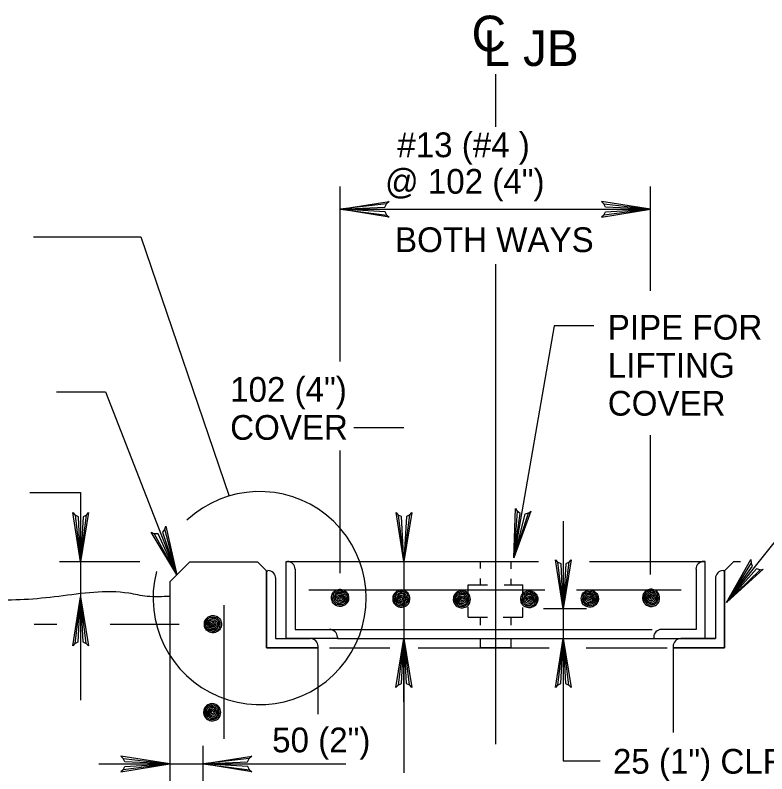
# Model space of a CAD drawing. Extents: x 638455 to 640199, y 298558 to 299152.
# Drawn here: x 639434 to 639536, y 298749 to 298852 of the extents above; entities that cross this region are included whole.
import ezdxf

# ---------------------------------------------------------------- set-up
doc = ezdxf.new("R2010")
doc.units = 0
for name, color, linetype in [('1', 7, 'Continuous'), ('2', 7, 'Continuous'), ('3', 7, 'Continuous')]:
    doc.layers.add(name, color=color, linetype=linetype)

msp = doc.modelspace()

# ---------------------------------------------------------------- linework, layer by layer
at = {"layer": '1'}
msp.add_line((639530.53, 298772.26), (639540.8, 298785.17), dxfattribs=at)
msp.add_arc((639467.17, 298772.88), 14.46, 165.5943, 133.0087, dxfattribs=at)
at = {"layer": '2'}
for p, q in [((639499.18, 298844), (639499.18, 298836.83)), ((639478.09, 298804.97), (639478.09, 298828.74)), ((639520.19, 298814.59), (639520.19, 298828.74)), ((639478.09, 298825.65), (639520.19, 298825.65)), ((639436.5, 298821.91), (639451.03, 298821.91)), ((639451.03, 298821.91), (639463.02, 298786.73)), ((639499.18, 298818.19), (639499.18, 298753.05)), ((639507.12, 298809.85), (639501.68, 298778.32)), ((639512.51, 298809.85), (639507.12, 298809.85)), ((639439.61, 298800.88), (639446.26, 298800.88)), ((639446.26, 298800.88), (639455.94, 298776.05)), ((639479.95, 298796.04), (639486.74, 298796.04)), ((639520.19, 298776.09), (639520.19, 298795)), ((639478.09, 298776.26), (639478.09, 298792.9)), ((639435.97, 298787.22), (639442.88, 298787.22)), ((639442.88, 298787.22), (639442.88, 298777.82)), ((639508.37, 298783.31), (639508.37, 298771.43)), ((639450.92, 298777.82), (639440, 298777.82)), ((639454.98, 298775.09), (639457.72, 298777.82)), ((639457.72, 298777.82), (639466.88, 298777.82)), ((639466.88, 298777.82), (639468.11, 298776.59)), ((639470.75, 298777.84), (639470.93, 298777.84)), ((639470.75, 298777.84), (639505.02, 298777.84)), ((639486.74, 298777.84), (639486.74, 298749.14)), ((639497.1, 298777.84), (639497.1, 298776.91)), ((639501.27, 298777.84), (639501.27, 298776.86)), ((639511.95, 298777.84), (639527.62, 298777.84)), ((639527.62, 298777.84), (639527.43, 298777.84)), ((639527.43, 298777.84), (639527.43, 298777.84)), ((639468.11, 298776.59), (639468.3, 298776.59)), ((639468.11, 298776.59), (639468.11, 298766.14)), ((639530.26, 298776.59), (639530.07, 298776.59)), ((639530.26, 298776.59), (639530.26, 298766.14)), ((639454.98, 298775.09), (639454.98, 298714.23)), ((639495.47, 298773.34), (639495.47, 298774.69)), ((639495.47, 298774.69), (639498.09, 298774.69)), ((639497.1, 298775.53), (639497.1, 298774.69)), ((639500.37, 298774.69), (639502.9, 298774.69)), ((639501.27, 298775.49), (639501.27, 298774.69)), ((639502.9, 298773.46), (639502.9, 298774.69)), ((639473.85, 298774.01), (639505.86, 298774.01)), ((639510.16, 298774.01), (639524.37, 298774.01)), ((639462.3, 298771.9), (639462.3, 298753.77)), ((639495.47, 298770.28), (639495.47, 298771.66)), ((639502.9, 298770.28), (639502.9, 298771.61)), ((639511.54, 298771.43), (639505.69, 298771.43)), ((639508.37, 298771.43), (639508.37, 298767.39)), ((639495.47, 298770.28), (639498.09, 298770.28)), ((639497.1, 298770.28), (639497.1, 298769.21)), ((639500.2, 298770.28), (639502.9, 298770.28)), ((639501.27, 298770.28), (639501.27, 298769.21)), ((639439.66, 298769.27), (639436.56, 298769.27)), ((639456.25, 298769.27), (639446.88, 298769.27)), ((639476.67, 298768.62), (639520.43, 298768.62)), ((639477.72, 298767.57), (639477.72, 298767.39)), ((639477.72, 298767.39), (639529.02, 298767.39)), ((639480.16, 298767.39), (639492.28, 298767.39)), ((639486.74, 298758.79), (639486.74, 298767.39)), ((639497.1, 298767.39), (639497.1, 298766.17)), ((639497.44, 298767.39), (639500.93, 298767.39)), ((639498.6, 298767.39), (639507.79, 298767.39)), ((639501.27, 298767.39), (639501.27, 298766.17)), ((639508.37, 298767.39), (639508.37, 298750.77)), ((639520.65, 298767.57), (639520.65, 298767.39)), ((639475.08, 298766.32), (639475.08, 298766.14)), ((639523.29, 298766.32), (639523.29, 298766.14)), ((639468.11, 298766.14), (639475.08, 298766.14)), ((639475.08, 298766.14), (639475.08, 298757.12)), ((639476.67, 298766.14), (639484.84, 298766.14)), ((639488.66, 298766.14), (639506.46, 298766.14)), ((639497.1, 298766.17), (639501.27, 298766.17)), ((639511.47, 298766.14), (639522.46, 298766.14)), ((639530.26, 298766.14), (639523.29, 298766.14)), ((639523.29, 298766.14), (639523.29, 298754.61)), ((639459.45, 298752.82), (639459.45, 298745.89)), ((639445.33, 298750.37), (639459.45, 298750.37)), ((639459.45, 298750.37), (639478.87, 298750.37)), ((639508.37, 298750.77), (639513.38, 298750.77))]:
    msp.add_line(p, q, dxfattribs=at)
for points in [[(639484.42, 298824.86), (639484.19, 298825.32), (639478.09, 298825.65), (639484.42, 298824.86), (639484.75, 298824.58), (639478.09, 298825.65), (639484.18, 298825.95), (639484.4, 298826.4), (639478.09, 298825.65), (639484.75, 298826.71), (639484.4, 298826.4)], [(639513.86, 298824.86), (639514.1, 298825.32), (639520.19, 298825.65), (639513.86, 298824.86), (639513.54, 298824.58), (639520.19, 298825.65), (639514.1, 298825.95), (639513.88, 298826.4), (639520.19, 298825.65), (639513.54, 298826.71), (639513.88, 298826.4)], [(639503.64, 298784.39), (639503.14, 298784.25), (639501.68, 298778.32), (639503.64, 298784.39), (639503.97, 298784.66), (639501.68, 298778.32), (639502.51, 298784.36), (639502.11, 298784.66), (639501.68, 298778.32), (639501.87, 298785.05), (639502.11, 298784.66)], [(639443.68, 298784.15), (639443.22, 298783.92), (639442.88, 298777.82), (639443.68, 298784.15), (639443.96, 298784.48), (639442.88, 298777.82), (639442.58, 298783.91), (639442.13, 298784.13), (639442.88, 298777.82), (639441.83, 298784.48), (639442.13, 298784.13)], [(639487.54, 298784.17), (639487.08, 298783.93), (639486.74, 298777.84), (639487.54, 298784.17), (639487.81, 298784.49), (639486.74, 298777.84), (639486.44, 298783.93), (639485.99, 298784.15), (639486.74, 298777.84), (639485.68, 298784.49), (639485.99, 298784.15)], [(639454.31, 298782.22), (639453.98, 298781.83), (639455.94, 298776.05), (639454.31, 298782.22), (639454.45, 298782.62), (639455.94, 298776.05), (639453.39, 298781.59), (639452.88, 298781.62), (639455.94, 298776.05), (639452.47, 298781.83), (639452.88, 298781.62)], [(639442.88, 298777.82), (639442.88, 298759.02)], [(639477.72, 298767.39), (639470.75, 298767.39), (639470.75, 298777.84)], [(639509.16, 298777.76), (639508.7, 298777.52), (639508.37, 298771.43), (639509.16, 298777.76), (639509.44, 298778.08), (639508.37, 298771.43), (639508.07, 298777.52), (639507.61, 298777.74), (639508.37, 298771.43), (639507.31, 298778.08), (639507.61, 298777.74)], [(639520.65, 298767.39), (639527.62, 298767.39), (639527.62, 298777.84)], [(639532.44, 298777.82), (639531.49, 298777.82), (639530.26, 298776.59)], [(639535.08, 298776.73), (639534.58, 298776.83), (639530.53, 298772.26), (639535.08, 298776.73), (639535.5, 298776.81), (639530.53, 298772.26), (639534.07, 298777.22), (639533.86, 298777.68), (639530.53, 298772.26), (639533.83, 298778.13), (639533.86, 298777.68)], [(639475.08, 298766.14), (639468.11, 298766.14), (639468.11, 298776.59)], [(639471.98, 298776.8), (639471.98, 298768.62), (639476.67, 298768.62)], [(639526.39, 298776.8), (639526.39, 298768.62), (639521.69, 298768.62)], [(639523.29, 298766.14), (639530.26, 298766.14), (639530.26, 298776.59)], [(639469.34, 298775.55), (639469.34, 298767.37), (639474.04, 298767.37)], [(639529.02, 298775.55), (639529.02, 298767.37), (639524.33, 298767.37)], [(639442.09, 298766.71), (639442.55, 298766.94), (639442.88, 298773.04), (639442.09, 298766.71), (639441.81, 298766.38), (639442.88, 298773.04), (639443.18, 298766.95), (639443.64, 298766.73), (639442.88, 298773.04), (639443.94, 298766.38), (639443.64, 298766.73)], [(639485.95, 298761.06), (639486.4, 298761.29), (639486.74, 298767.39), (639485.95, 298761.06), (639485.67, 298760.73), (639486.74, 298767.39), (639487.04, 298761.3), (639487.5, 298761.08), (639486.74, 298767.39), (639487.8, 298760.73), (639487.5, 298761.08)], [(639507.57, 298761.06), (639508.03, 298761.29), (639508.37, 298767.39), (639507.57, 298761.06), (639507.3, 298760.73), (639508.37, 298767.39), (639508.67, 298761.3), (639509.12, 298761.07), (639508.37, 298767.39), (639509.42, 298760.73), (639509.12, 298761.07)], [(639448.65, 298749.58), (639448.89, 298750.04), (639454.98, 298750.37), (639448.65, 298749.58), (639448.33, 298749.3), (639454.98, 298750.37), (639448.89, 298750.67), (639448.67, 298751.12), (639454.98, 298750.37), (639448.33, 298751.43), (639448.67, 298751.12)], [(639465.79, 298749.58), (639465.55, 298750.04), (639459.45, 298750.37), (639465.79, 298749.58), (639466.11, 298749.3), (639459.45, 298750.37), (639465.54, 298750.67), (639465.77, 298751.12), (639459.45, 298750.37), (639466.11, 298751.43), (639465.77, 298751.12)]]:
    msp.add_lwpolyline(points, dxfattribs=at)
for centre, start, end in [((639470.93, 298776.8), 0, 90), ((639527.43, 298776.8), 90, 180), ((639468.3, 298775.55), 0, 90), ((639530.07, 298775.55), 90, 180), ((639476.67, 298767.57), 0, 90), ((639521.69, 298767.57), 90, 180), ((639474.04, 298766.32), 0, 90), ((639524.33, 298766.32), 90, 180)]:
    msp.add_arc(centre, 1.05, start, end, dxfattribs=at)
for points in [[(639455, 298773.11), (639451.9, 298773.11), (639449.41, 298773.53), (639439.9, 298773.11), (639430.6, 298772.7), (639416.33, 298773.11), (639412.61, 298772.49), (639410.96, 298773.53), (639403.1, 298773.32), (639402.56, 298773.5)], [(639478.08, 298772.91), (639478.14, 298773.02), (639478.23, 298773.01), (639478.25, 298772.83), (639478.09, 298772.73), (639477.89, 298772.83), (639477.9, 298773.01), (639478.01, 298773.12), (639478.23, 298773.14), (639478.38, 298773.02), (639478.46, 298772.84), (639478.35, 298772.59), (639478.1, 298772.53), (639477.84, 298772.61), (639477.69, 298772.78), (639477.71, 298773.07), (639477.85, 298773.25), (639478.09, 298773.32), (639478.3, 298773.27), (639478.48, 298773.17), (639478.55, 298772.98), (639478.6, 298772.74), (639478.55, 298772.52), (639478.34, 298772.37), (639478.01, 298772.31), (639477.67, 298772.45), (639477.49, 298772.7), (639477.49, 298773.02), (639477.6, 298773.3), (639477.85, 298773.49), (639478.23, 298773.51), (639478.5, 298773.36), (639478.66, 298773.1), (639478.76, 298772.83), (639478.72, 298772.5), (639478.5, 298772.27), (639478.18, 298772.13), (639477.68, 298772.21), (639477.36, 298772.49), (639477.3, 298772.87), (639477.36, 298773.25), (639477.58, 298773.55), (639477.87, 298773.67), (639478.34, 298773.66), (639478.7, 298773.45), (639478.87, 298773.14), (639478.91, 298772.81), (639478.89, 298772.53), (639478.77, 298772.23), (639478.48, 298772.02), (639478, 298771.95), (639477.57, 298772.07), (639477.25, 298772.36), (639477.12, 298772.71), (639477.15, 298773.15), (639477.3, 298773.57), (639477.54, 298773.74), (639477.96, 298773.89), (639478.4, 298773.83), (639478.71, 298773.69), (639478.95, 298773.42), (639479.07, 298773.13), (639479.07, 298772.83), (639479.06, 298772.5), (639478.98, 298772.19), (639478.83, 298772.02), (639478.59, 298771.86), (639478.35, 298771.77), (639478.1, 298771.74), (639477.8, 298771.78), (639477.49, 298771.88), (639477.23, 298772.08), (639477.05, 298772.33), (639476.96, 298772.64), (639476.91, 298772.94), (639476.98, 298773.27), (639477.1, 298773.55), (639477.32, 298773.8), (639477.58, 298773.96), (639477.85, 298774.06), (639478.16, 298774.07), (639478.52, 298773.98), (639478.83, 298773.8), (639479.01, 298773.6), (639479.17, 298773.35), (639479.22, 298773.09), (639479.23, 298772.78), (639479.17, 298772.45), (639479.07, 298772.3), (639478.87, 298772.08)], [(639486.39, 298772.81), (639486.33, 298772.92), (639486.24, 298772.91), (639486.23, 298772.72), (639486.39, 298772.63), (639486.58, 298772.72), (639486.57, 298772.91), (639486.47, 298773.02), (639486.24, 298773.04), (639486.09, 298772.92), (639486.02, 298772.73), (639486.13, 298772.48), (639486.37, 298772.43), (639486.64, 298772.51), (639486.78, 298772.68), (639486.76, 298772.97), (639486.63, 298773.15), (639486.39, 298773.21), (639486.17, 298773.17), (639485.99, 298773.06), (639485.92, 298772.88), (639485.88, 298772.63), (639485.93, 298772.41), (639486.14, 298772.27), (639486.46, 298772.21), (639486.81, 298772.35), (639486.98, 298772.59), (639486.98, 298772.92), (639486.87, 298773.2), (639486.63, 298773.39), (639486.24, 298773.41), (639485.97, 298773.26), (639485.81, 298773), (639485.71, 298772.72), (639485.75, 298772.4), (639485.97, 298772.16), (639486.29, 298772.03), (639486.79, 298772.11), (639487.11, 298772.38), (639487.18, 298772.77), (639487.11, 298773.15), (639486.89, 298773.44), (639486.6, 298773.56), (639486.14, 298773.55), (639485.78, 298773.35), (639485.6, 298773.04), (639485.56, 298772.71), (639485.59, 298772.43), (639485.7, 298772.13), (639485.99, 298771.91), (639486.48, 298771.85), (639486.91, 298771.97), (639487.22, 298772.26), (639487.35, 298772.61), (639487.32, 298773.05), (639487.18, 298773.46), (639486.94, 298773.64), (639486.51, 298773.79), (639486.07, 298773.73), (639485.76, 298773.59), (639485.53, 298773.31), (639485.4, 298773.03), (639485.4, 298772.72), (639485.42, 298772.4), (639485.49, 298772.09), (639485.65, 298771.91), (639485.89, 298771.76), (639486.13, 298771.67), (639486.37, 298771.64), (639486.67, 298771.68), (639486.98, 298771.78), (639487.25, 298771.98), (639487.43, 298772.22), (639487.52, 298772.54), (639487.56, 298772.83), (639487.49, 298773.17), (639487.37, 298773.44), (639487.16, 298773.69), (639486.89, 298773.86), (639486.63, 298773.96), (639486.32, 298773.97), (639485.95, 298773.88), (639485.65, 298773.69), (639485.46, 298773.5), (639485.3, 298773.25), (639485.25, 298772.98), (639485.24, 298772.68), (639485.3, 298772.35), (639485.4, 298772.2), (639485.6, 298771.98)], [(639494.6, 298772.72), (639494.54, 298772.83), (639494.45, 298772.82), (639494.44, 298772.64), (639494.6, 298772.54), (639494.79, 298772.64), (639494.79, 298772.82), (639494.68, 298772.93), (639494.45, 298772.95), (639494.3, 298772.83), (639494.23, 298772.65), (639494.34, 298772.4), (639494.58, 298772.34), (639494.85, 298772.43), (639494.99, 298772.59), (639494.97, 298772.88), (639494.84, 298773.06), (639494.6, 298773.13), (639494.38, 298773.08), (639494.2, 298772.98), (639494.13, 298772.79), (639494.09, 298772.55), (639494.14, 298772.33), (639494.35, 298772.18), (639494.67, 298772.12), (639495.02, 298772.27), (639495.19, 298772.5), (639495.19, 298772.83), (639495.08, 298773.12), (639494.84, 298773.3), (639494.45, 298773.33), (639494.18, 298773.17), (639494.02, 298772.91), (639493.92, 298772.64), (639493.96, 298772.31), (639494.18, 298772.08), (639494.5, 298771.94), (639495, 298772.02), (639495.32, 298772.3), (639495.39, 298772.68), (639495.32, 298773.06), (639495.1, 298773.36), (639494.81, 298773.48), (639494.35, 298773.47), (639493.99, 298773.26), (639493.81, 298772.95), (639493.77, 298772.63), (639493.8, 298772.34), (639493.91, 298772.04), (639494.2, 298771.83), (639494.69, 298771.76), (639495.12, 298771.88), (639495.43, 298772.18), (639495.56, 298772.52), (639495.53, 298772.97), (639495.39, 298773.38), (639495.15, 298773.55), (639494.72, 298773.71), (639494.28, 298773.64), (639493.97, 298773.5), (639493.74, 298773.23), (639493.61, 298772.94), (639493.61, 298772.64), (639493.63, 298772.31), (639493.7, 298772), (639493.86, 298771.83), (639494.1, 298771.68), (639494.34, 298771.59), (639494.58, 298771.55), (639494.88, 298771.59), (639495.19, 298771.69), (639495.45, 298771.89), (639495.64, 298772.14), (639495.73, 298772.45), (639495.77, 298772.74), (639495.7, 298773.08), (639495.58, 298773.36), (639495.37, 298773.61), (639495.1, 298773.78), (639494.84, 298773.87), (639494.53, 298773.88), (639494.16, 298773.79), (639493.86, 298773.61), (639493.67, 298773.41), (639493.51, 298773.16), (639493.46, 298772.9), (639493.45, 298772.59), (639493.51, 298772.27), (639493.61, 298772.11), (639493.81, 298771.89)], [(639503.76, 298772.72), (639503.82, 298772.83), (639503.91, 298772.82), (639503.93, 298772.64), (639503.77, 298772.54), (639503.57, 298772.64), (639503.58, 298772.82), (639503.69, 298772.93), (639503.91, 298772.95), (639504.06, 298772.83), (639504.14, 298772.65), (639504.03, 298772.4), (639503.79, 298772.34), (639503.52, 298772.43), (639503.38, 298772.59), (639503.4, 298772.88), (639503.53, 298773.06), (639503.77, 298773.13), (639503.98, 298773.08), (639504.16, 298772.98), (639504.24, 298772.79), (639504.28, 298772.55), (639504.23, 298772.33), (639504.02, 298772.18), (639503.7, 298772.12), (639503.35, 298772.27), (639503.18, 298772.5), (639503.18, 298772.83), (639503.29, 298773.12), (639503.53, 298773.3), (639503.91, 298773.33), (639504.18, 298773.17), (639504.35, 298772.91), (639504.45, 298772.64), (639504.4, 298772.31), (639504.18, 298772.08), (639503.87, 298771.94), (639503.36, 298772.02), (639503.05, 298772.3), (639502.98, 298772.68), (639503.05, 298773.06), (639503.27, 298773.36), (639503.56, 298773.48), (639504.02, 298773.47), (639504.38, 298773.26), (639504.55, 298772.95), (639504.6, 298772.63), (639504.57, 298772.34), (639504.46, 298772.04), (639504.16, 298771.83), (639503.68, 298771.76), (639503.25, 298771.88), (639502.93, 298772.18), (639502.81, 298772.52), (639502.84, 298772.97), (639502.98, 298773.38), (639503.22, 298773.55), (639503.65, 298773.71), (639504.09, 298773.64), (639504.39, 298773.5), (639504.63, 298773.23), (639504.75, 298772.94), (639504.75, 298772.64), (639504.74, 298772.31), (639504.67, 298772), (639504.51, 298771.83), (639504.27, 298771.68), (639504.03, 298771.59), (639503.79, 298771.55), (639503.48, 298771.59), (639503.18, 298771.69), (639502.91, 298771.89), (639502.73, 298772.14), (639502.64, 298772.45), (639502.6, 298772.74), (639502.66, 298773.08), (639502.78, 298773.36), (639503, 298773.61), (639503.27, 298773.78), (639503.53, 298773.87), (639503.84, 298773.88), (639504.21, 298773.79), (639504.51, 298773.61), (639504.7, 298773.41), (639504.85, 298773.16), (639504.91, 298772.9), (639504.91, 298772.59), (639504.85, 298772.27), (639504.75, 298772.11), (639504.55, 298771.89)], [(639511.98, 298772.81), (639512.03, 298772.92), (639512.12, 298772.91), (639512.14, 298772.72), (639511.98, 298772.63), (639511.78, 298772.72), (639511.79, 298772.91), (639511.9, 298773.02), (639512.12, 298773.04), (639512.27, 298772.92), (639512.35, 298772.73), (639512.24, 298772.48), (639512, 298772.43), (639511.73, 298772.51), (639511.59, 298772.68), (639511.6, 298772.97), (639511.74, 298773.15), (639511.98, 298773.21), (639512.19, 298773.17), (639512.37, 298773.06), (639512.45, 298772.88), (639512.49, 298772.63), (639512.44, 298772.41), (639512.23, 298772.27), (639511.91, 298772.21), (639511.56, 298772.35), (639511.39, 298772.59), (639511.39, 298772.92), (639511.5, 298773.2), (639511.74, 298773.39), (639512.12, 298773.41), (639512.39, 298773.26), (639512.56, 298773), (639512.66, 298772.72), (639512.61, 298772.4), (639512.39, 298772.16), (639512.08, 298772.03), (639511.57, 298772.11), (639511.26, 298772.38), (639511.19, 298772.77), (639511.26, 298773.15), (639511.48, 298773.44), (639511.77, 298773.56), (639512.23, 298773.55), (639512.59, 298773.35), (639512.77, 298773.04), (639512.81, 298772.71), (639512.78, 298772.43), (639512.67, 298772.13), (639512.37, 298771.91), (639511.89, 298771.85), (639511.46, 298771.97), (639511.14, 298772.26), (639511.02, 298772.61), (639511.05, 298773.05), (639511.19, 298773.46), (639511.43, 298773.64), (639511.85, 298773.79), (639512.29, 298773.73), (639512.6, 298773.59), (639512.84, 298773.31), (639512.97, 298773.03), (639512.97, 298772.72), (639512.95, 298772.4), (639512.88, 298772.09), (639512.72, 298771.91), (639512.48, 298771.76), (639512.24, 298771.67), (639512, 298771.64), (639511.69, 298771.68), (639511.39, 298771.78), (639511.12, 298771.98), (639510.94, 298772.22), (639510.85, 298772.54), (639510.81, 298772.83), (639510.87, 298773.17), (639510.99, 298773.44), (639511.21, 298773.69), (639511.48, 298773.86), (639511.74, 298773.96), (639512.05, 298773.97), (639512.42, 298773.88), (639512.72, 298773.69), (639512.91, 298773.5), (639513.06, 298773.25), (639513.12, 298772.98), (639513.13, 298772.68), (639513.06, 298772.35), (639512.97, 298772.2), (639512.77, 298771.98)], [(639520.29, 298772.91), (639520.23, 298773.02), (639520.14, 298773.01), (639520.12, 298772.83), (639520.28, 298772.73), (639520.48, 298772.83), (639520.47, 298773.01), (639520.36, 298773.12), (639520.14, 298773.14), (639519.99, 298773.02), (639519.91, 298772.84), (639520.02, 298772.59), (639520.26, 298772.53), (639520.53, 298772.61), (639520.68, 298772.78), (639520.66, 298773.07), (639520.52, 298773.25), (639520.28, 298773.32), (639520.07, 298773.27), (639519.89, 298773.17), (639519.81, 298772.98), (639519.77, 298772.74), (639519.82, 298772.52), (639520.03, 298772.37), (639520.35, 298772.31), (639520.7, 298772.45), (639520.88, 298772.7), (639520.88, 298773.02), (639520.76, 298773.3), (639520.52, 298773.49), (639520.14, 298773.51), (639519.87, 298773.36), (639519.7, 298773.1), (639519.6, 298772.83), (639519.65, 298772.5), (639519.87, 298772.27), (639520.19, 298772.13), (639520.69, 298772.21), (639521, 298772.49), (639521.07, 298772.87), (639521, 298773.25), (639520.79, 298773.55), (639520.49, 298773.67), (639520.03, 298773.66), (639519.67, 298773.45), (639519.5, 298773.14), (639519.45, 298772.81), (639519.48, 298772.53), (639519.6, 298772.23), (639519.89, 298772.02), (639520.37, 298771.95), (639520.8, 298772.07), (639521.12, 298772.36), (639521.24, 298772.71), (639521.21, 298773.15), (639521.07, 298773.57), (639520.83, 298773.74), (639520.41, 298773.89), (639519.96, 298773.83), (639519.66, 298773.69), (639519.42, 298773.42), (639519.3, 298773.13), (639519.3, 298772.83), (639519.31, 298772.5), (639519.39, 298772.19), (639519.54, 298772.02), (639519.78, 298771.86), (639520.02, 298771.77), (639520.26, 298771.74), (639520.57, 298771.78), (639520.88, 298771.88), (639521.14, 298772.08), (639521.32, 298772.33), (639521.41, 298772.64), (639521.45, 298772.94), (639521.39, 298773.27), (639521.27, 298773.55), (639521.05, 298773.8), (639520.79, 298773.96), (639520.52, 298774.06), (639520.21, 298774.07), (639519.84, 298773.98), (639519.54, 298773.8), (639519.35, 298773.6), (639519.2, 298773.35), (639519.15, 298773.09), (639519.14, 298772.78), (639519.2, 298772.45), (639519.3, 298772.3), (639519.5, 298772.08)], [(639460.83, 298769.34), (639460.76, 298769.22), (639460.68, 298769.24), (639460.66, 298769.42), (639460.82, 298769.52), (639461.02, 298769.42), (639461.01, 298769.24), (639460.9, 298769.13), (639460.68, 298769.11), (639460.53, 298769.22), (639460.45, 298769.41), (639460.56, 298769.66), (639460.8, 298769.71), (639461.07, 298769.64), (639461.21, 298769.47), (639461.19, 298769.18), (639461.06, 298769), (639460.82, 298768.93), (639460.6, 298768.97), (639460.43, 298769.08), (639460.35, 298769.27), (639460.31, 298769.51), (639460.36, 298769.74), (639460.57, 298769.88), (639460.89, 298769.94), (639461.24, 298769.8), (639461.41, 298769.56), (639461.41, 298769.22), (639461.3, 298768.95), (639461.06, 298768.76), (639460.68, 298768.73), (639460.4, 298768.89), (639460.24, 298769.15), (639460.14, 298769.42), (639460.19, 298769.75), (639460.4, 298769.99), (639460.72, 298770.12), (639461.23, 298770.04), (639461.54, 298769.76), (639461.61, 298769.38), (639461.54, 298769), (639461.32, 298768.7), (639461.03, 298768.58), (639460.57, 298768.59), (639460.21, 298768.8), (639460.04, 298769.11), (639459.99, 298769.44), (639460.02, 298769.71), (639460.13, 298770.02), (639460.43, 298770.23), (639460.91, 298770.3), (639461.34, 298770.18), (639461.65, 298769.89), (639461.78, 298769.54), (639461.75, 298769.1), (639461.61, 298768.68), (639461.37, 298768.51), (639460.94, 298768.36), (639460.5, 298768.42), (639460.19, 298768.56), (639459.96, 298768.83), (639459.83, 298769.12), (639459.83, 298769.42), (639459.85, 298769.75), (639459.92, 298770.06), (639460.08, 298770.23), (639460.32, 298770.39), (639460.56, 298770.48), (639460.8, 298770.51), (639461.1, 298770.46), (639461.41, 298770.37), (639461.68, 298770.17), (639461.86, 298769.92), (639461.95, 298769.61), (639461.99, 298769.31), (639461.93, 298768.97), (639461.8, 298768.7), (639461.59, 298768.45), (639461.32, 298768.28), (639461.06, 298768.19), (639460.75, 298768.18), (639460.38, 298768.27), (639460.08, 298768.45), (639459.89, 298768.65), (639459.74, 298768.9), (639459.68, 298769.16), (639459.67, 298769.47), (639459.74, 298769.8), (639459.83, 298769.95), (639460.04, 298770.17)], [(639460.72, 298757.38), (639460.67, 298757.49), (639460.58, 298757.48), (639460.56, 298757.29), (639460.72, 298757.2), (639460.92, 298757.29), (639460.91, 298757.48), (639460.8, 298757.59), (639460.58, 298757.61), (639460.42, 298757.49), (639460.35, 298757.3), (639460.46, 298757.05), (639460.7, 298757), (639460.97, 298757.08), (639461.11, 298757.25), (639461.1, 298757.54), (639460.96, 298757.72), (639460.72, 298757.79), (639460.51, 298757.74), (639460.33, 298757.63), (639460.25, 298757.45), (639460.21, 298757.21), (639460.26, 298756.98), (639460.47, 298756.84), (639460.79, 298756.78), (639461.14, 298756.92), (639461.31, 298757.16), (639461.31, 298757.49), (639461.2, 298757.77), (639460.96, 298757.96), (639460.58, 298757.98), (639460.31, 298757.83), (639460.14, 298757.57), (639460.04, 298757.29), (639460.09, 298756.97), (639460.31, 298756.73), (639460.62, 298756.6), (639461.13, 298756.68), (639461.44, 298756.96), (639461.51, 298757.34), (639461.44, 298757.72), (639461.22, 298758.01), (639460.93, 298758.13), (639460.47, 298758.13), (639460.11, 298757.92), (639459.93, 298757.61), (639459.89, 298757.28), (639459.92, 298757), (639460.03, 298756.7), (639460.33, 298756.48), (639460.81, 298756.42), (639461.24, 298756.54), (639461.55, 298756.83), (639461.68, 298757.18), (639461.65, 298757.62), (639461.51, 298758.04), (639461.27, 298758.21), (639460.85, 298758.36), (639460.4, 298758.3), (639460.1, 298758.16), (639459.86, 298757.88), (639459.73, 298757.6), (639459.73, 298757.29), (639459.75, 298756.97), (639459.82, 298756.66), (639459.98, 298756.48), (639460.22, 298756.33), (639460.46, 298756.24), (639460.7, 298756.21), (639461.01, 298756.25), (639461.31, 298756.35), (639461.58, 298756.55), (639461.76, 298756.8), (639461.85, 298757.11), (639461.89, 298757.4), (639461.83, 298757.74), (639461.71, 298758.01), (639461.49, 298758.26), (639461.22, 298758.43), (639460.96, 298758.53), (639460.65, 298758.54), (639460.28, 298758.45), (639459.98, 298758.26), (639459.79, 298758.07), (639459.64, 298757.82), (639459.58, 298757.55), (639459.57, 298757.25), (639459.64, 298756.92), (639459.73, 298756.77), (639459.93, 298756.55)]]:
    msp.add_spline(points, degree=3, dxfattribs=at)

# ---------------------------------------------------------------- texts
at = {"layer": '3'}
for s, height, p in [('C', 4.84, (639495.93, 298847.09)), ('L JB', 4.838, (639497.52, 298845.1)), ('#13 (#4 )', 3.36, (639485.85, 298832.72)), ('@ 102 (4")', 3.36, (639484.19, 298827.76)), ('BOTH WAYS', 3.36, (639485.54, 298819.84)), ('PIPE FOR', 3.36, (639514.41, 298807.96)), ('LIFTING', 3.36, (639514.41, 298802.8)), ('102 (4")', 3.36, (639463.17, 298799.52)), ('COVER', 3.36, (639514.41, 298797.64)), ('COVER', 3.36, (639463.17, 298794.36)), ('50 (2")', 3.36, (639468.87, 298751.94)), ('25 (1") CLR', 3.36, (639515.11, 298749.04))]:
    msp.add_text(s, height=height, dxfattribs=at).set_placement(p)

doc.saveas('drawing.dxf')
